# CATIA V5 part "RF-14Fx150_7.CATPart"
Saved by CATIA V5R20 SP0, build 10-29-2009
Part number: _RF-14Fx150
Definition: NONE
Nomenclature: _RF-14Fx150
Source: Unknown
Description: PART-_RF-14Fx150-DESC
Bounding box of the stored display mesh (mm): x -150 to 24.5, y -7.65 to 7.65, z -7.65 to 7.65
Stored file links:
  C:\Users\Utente\Desktop\IO LAVORO\3D X SITO CF\X SITO\PLASTICA\RFF\RF-14Fx150_7.CATPart

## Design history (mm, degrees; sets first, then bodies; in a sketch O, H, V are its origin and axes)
Body1 "_RF-14Fx150" (main body)
  Solid1: solid without history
